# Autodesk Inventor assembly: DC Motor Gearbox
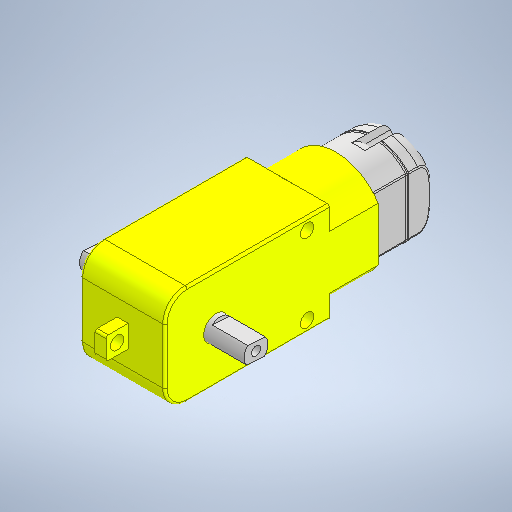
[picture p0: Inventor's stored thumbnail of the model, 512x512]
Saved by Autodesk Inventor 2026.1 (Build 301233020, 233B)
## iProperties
Created: 2019-04
Part Number: DC Motor Gearbox
Description: STEP AP203
Document SubType Name: Assembly
Designer: hp
Title: DC Motor Gearbox.STEP
Revision Number: ANY
Sending System: SolidWorks 2018
Preprocessor: SwSTEP 2.0
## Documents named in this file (4)
- C:\Users\hp\Documents\Inventor\DOM1_CartesianRobot\DC Motor Gearbox\DC Motor Gearbox\DC Motor Gearbox.iam
- C:\Users\hp\Documents\Inventor\DOM1_CartesianRobot\DC Motor Gearbox\DC Motor Gearbox\Gearbox.ipt
- C:\Users\hp\Documents\Inventor\DOM1_CartesianRobot\DC Motor Gearbox\DC Motor Gearbox\output shaft.ipt
- C:\Users\hp\Documents\Inventor\DOM1_CartesianRobot\DC Motor Gearbox\DC Motor Gearbox\motor.ipt
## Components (3 placed, 3 different names)
1. Gearbox_1
2. output shaft_2
3. motor_3
